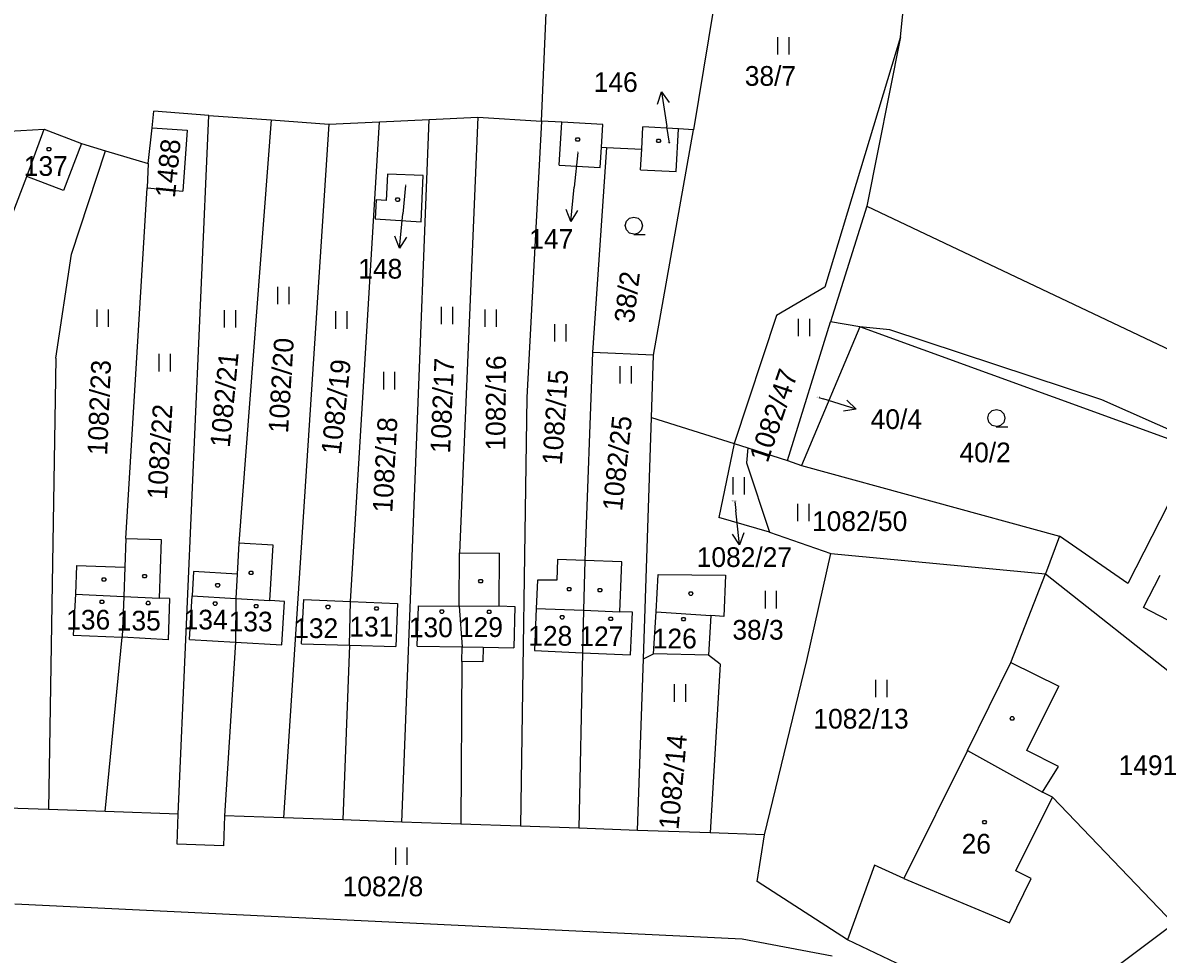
# Model space of a CAD drawing. Extents: x -850689 to -847910, y -1058374 to -1054747.
# Drawn here: x -849424.1 to -849326.1, y -1056255.5 to -1056175.1 of the extents above; entities that cross this region are included whole.
import ezdxf

# ---------------------------------------------------------------- set-up
doc = ezdxf.new("R2010")
doc.units = 0
for name, color, linetype in [('KN_HRANICE', 7, 'Continuous'), ('KN_KULTURY', 7, 'Continuous'), ('KN_PARCELY', 7, 'Continuous'), ('KN_SLUCKY', 7, 'Continuous'), ('KN_STAVEBNI', 7, 'Continuous')]:
    doc.layers.add(name, color=color, linetype=linetype)

# ---------------------------------------------------------------- blocks, each defined once
blk = doc.blocks.new('304')
blk.add_lwpolyline([(0, 0), (-0.38, 0.1), (-0.65, 0.37), (-0.75, 0.74), (-0.65, 1.11), (-0.38, 1.38), (-0.01, 1.48), (0.36, 1.38), (0.63, 1.11), (0.73, 0.73), (0.63, 0.35), (0.36, 0.08), (-0.02, -0.02), (0.98, -0.02)])
blk = doc.blocks.new('306')
for p, q in [((-0.5, 1.5), (-0.5, 0)), ((0.5, 0), (0.5, 1.5))]:
    blk.add_line(p, q)
blk = doc.blocks.new('NAHRADNI_SYMBOL')
blk.add_lwpolyline([(0.09, 0.15), (0.18, 0), (0.09, -0.15), (-0.09, -0.15), (-0.18, 0), (-0.09, 0.15), (0.09, 0.15)])
blk = doc.blocks.new('10292')
blk.add_line((0, 3), (0, 0))
blk.add_lwpolyline([(-0.5, 2), (0, 3), (0.5, 2)])
blk = doc.blocks.new('402')
blk.add_lwpolyline([(0.09, 0.15), (0.18, 0), (0.09, -0.15), (-0.09, -0.15), (-0.18, 0), (-0.09, 0.15), (0.09, 0.15)])

msp = doc.modelspace()

# ---------------------------------------------------------------- linework, layer by layer
at = {"layer": 'KN_HRANICE'}
for p, q in [((-849348.36, -1056176.35), (-849346.5, -1056157.31)), ((-849379.32, -1056183.62), (-849378.74, -1056169.41)), ((-849364.51, -1056173.91), (-849366.23, -1056184.36)), ((-849348.36, -1056176.35), (-849354.89, -1056197.95)), ((-849348.36, -1056176.35), (-849351.28, -1056190.95)), ((-849412.91, -1056184.19), (-849412.76, -1056182.77)), ((-849408.02, -1056183.12), (-849412.76, -1056182.77)), ((-849410.67, -1056243.39), (-849408.02, -1056183.12)), ((-849408.02, -1056183.12), (-849402.65, -1056183.52)), ((-849402.65, -1056183.52), (-849405.42, -1056220.02)), ((-849402.65, -1056183.52), (-849397.67, -1056183.89)), ((-849397.67, -1056183.89), (-849393.31, -1056183.68)), ((-849395.79, -1056225.05), (-849393.31, -1056183.68)), ((-849393.31, -1056183.68), (-849389.01, -1056183.48)), ((-849391.38, -1056244.07), (-849389.01, -1056183.48)), ((-849389.01, -1056183.48), (-849384.81, -1056183.28)), ((-849384.81, -1056183.28), (-849386.41, -1056220.84)), ((-849384.81, -1056183.28), (-849379.32, -1056183.62)), ((-849379.32, -1056183.62), (-849380.59, -1056207.46)), ((-849377.59, -1056183.72), (-849379.32, -1056183.62)), ((-849377.8, -1056187.41), (-849377.59, -1056183.72)), ((-849374.05, -1056183.92), (-849377.59, -1056183.72)), ((-849437.73, -1056185.24), (-849422.22, -1056184.31)), ((-849423.72, -1056188.39), (-849422.22, -1056184.31)), ((-849422.22, -1056184.31), (-849418.99, -1056185.55)), ((-849413.25, -1056187.28), (-849412.91, -1056184.19)), ((-849412.91, -1056184.19), (-849409.88, -1056184.39)), ((-849409.88, -1056184.39), (-849410.26, -1056189.65)), ((-849397.67, -1056183.89), (-849401.57, -1056243.71)), ((-849374.16, -1056185.87), (-849374.05, -1056183.92)), ((-849370.69, -1056186.03), (-849370.58, -1056184.12)), ((-849367.51, -1056184.29), (-849370.58, -1056184.12)), ((-849369.66, -1056203.79), (-849366.23, -1056184.36)), ((-849367.72, -1056187.96), (-849367.51, -1056184.29)), ((-849366.23, -1056184.36), (-849367.51, -1056184.29)), ((-849418.99, -1056185.55), (-849420.56, -1056189.61)), ((-849418.99, -1056185.55), (-849416.94, -1056186.17)), ((-849419.86, -1056195.08), (-849416.94, -1056186.17)), ((-849416.94, -1056186.17), (-849413.25, -1056187.28)), ((-849373.73, -1056185.89), (-849374.92, -1056203.58)), ((-849374.26, -1056187.61), (-849374.16, -1056185.87)), ((-849374.16, -1056185.87), (-849373.73, -1056185.89)), ((-849373.73, -1056185.89), (-849370.69, -1056186.03)), ((-849370.79, -1056187.81), (-849370.69, -1056186.03)), ((-849413.25, -1056187.28), (-849413.34, -1056189.38)), ((-849377.8, -1056187.41), (-849374.26, -1056187.61)), ((-849425.74, -1056193.65), (-849423.72, -1056188.39)), ((-849420.56, -1056189.61), (-849423.72, -1056188.39)), ((-849392.61, -1056188.18), (-849392.73, -1056190.46)), ((-849389.53, -1056188.31), (-849392.61, -1056188.18)), ((-849389.71, -1056192.31), (-849389.53, -1056188.31)), ((-849370.79, -1056187.81), (-849367.72, -1056187.96)), ((-849415.18, -1056219.61), (-849413.34, -1056189.38)), ((-849413.34, -1056189.38), (-849410.26, -1056189.65)), ((-849393.59, -1056190.4), (-849393.69, -1056192.04)), ((-849392.73, -1056190.46), (-849393.59, -1056190.4)), ((-849351.28, -1056190.95), (-849354.41, -1056200.92)), ((-849351.28, -1056190.95), (-849317.91, -1056206.78)), ((-849393.69, -1056192.04), (-849389.71, -1056192.31)), ((-849421.21, -1056204.05), (-849419.86, -1056195.08)), ((-849354.89, -1056197.95), (-849359.05, -1056200.39)), ((-849359.05, -1056200.39), (-849362.71, -1056211.43)), ((-849358.1, -1056212.88), (-849354.41, -1056200.92)), ((-849351.88, -1056201.36), (-849354.41, -1056200.92)), ((-849351.88, -1056201.36), (-849356.9, -1056213.31)), ((-849321.95, -1056212.23), (-849351.88, -1056201.36)), ((-849349.3, -1056201.62), (-849351.88, -1056201.36)), ((-849331, -1056207.66), (-849349.3, -1056201.62)), ((-849421.21, -1056204.05), (-849421.86, -1056243)), ((-849374.92, -1056203.58), (-849375.6, -1056221.52)), ((-849369.66, -1056203.79), (-849374.92, -1056203.58)), ((-849369.84, -1056209.17), (-849369.66, -1056203.79)), ((-849380.59, -1056207.46), (-849381.14, -1056244.42)), ((-849309.67, -1056217.15), (-849331, -1056207.66)), ((-849370.54, -1056230), (-849369.84, -1056209.17)), ((-849369.84, -1056209.17), (-849362.71, -1056211.43)), ((-849362.71, -1056211.43), (-849364.05, -1056217.8)), ((-849362.71, -1056211.43), (-849361.54, -1056211.8)), ((-849361.54, -1056211.8), (-849361.64, -1056213.08)), ((-849361.54, -1056211.8), (-849358.1, -1056212.88)), ((-849361.64, -1056213.08), (-849359.68, -1056219.08)), ((-849358.1, -1056212.88), (-849356.9, -1056213.31)), ((-849356.9, -1056213.31), (-849334.65, -1056219.42)), ((-849323.51, -1056213.18), (-849328.75, -1056223.5)), ((-849359.68, -1056219.08), (-849364.05, -1056217.8)), ((-849415.18, -1056219.61), (-849415.26, -1056222.08)), ((-849415.18, -1056219.61), (-849412.13, -1056219.71)), ((-849412.13, -1056219.71), (-849412.3, -1056224.75)), ((-849359.68, -1056219.08), (-849354.38, -1056220.91)), ((-849334.65, -1056219.42), (-849335.86, -1056222.66)), ((-849328.75, -1056223.5), (-849334.65, -1056219.42)), ((-849405.42, -1056220.02), (-849405.57, -1056222.7)), ((-849402.48, -1056220.19), (-849405.42, -1056220.02)), ((-849402.75, -1056224.96), (-849402.48, -1056220.19)), ((-849386.44, -1056225.44), (-849386.41, -1056220.84)), ((-849386.41, -1056220.84), (-849382.96, -1056220.88)), ((-849382.99, -1056225.42), (-849382.96, -1056220.88)), ((-849356.44, -1056230.13), (-849354.38, -1056220.91)), ((-849354.38, -1056220.91), (-849335.86, -1056222.66)), ((-849377.94, -1056221.42), (-849378.01, -1056223.21)), ((-849375.6, -1056221.52), (-849377.94, -1056221.42)), ((-849375.6, -1056221.52), (-849375.7, -1056225.8)), ((-849372.39, -1056221.63), (-849375.6, -1056221.52)), ((-849372.57, -1056225.93), (-849372.39, -1056221.63)), ((-849419.43, -1056221.94), (-849419.51, -1056224.41)), ((-849419.43, -1056221.94), (-849415.26, -1056222.08)), ((-849415.26, -1056222.08), (-849415.35, -1056224.61)), ((-849409.34, -1056222.47), (-849409.46, -1056224.57)), ((-849405.57, -1056222.7), (-849409.34, -1056222.47)), ((-849405.57, -1056222.7), (-849405.69, -1056224.8)), ((-849369.45, -1056225.94), (-849369.26, -1056222.73)), ((-849369.26, -1056222.73), (-849363.46, -1056222.79)), ((-849363.46, -1056222.79), (-849363.6, -1056226.34)), ((-849338.84, -1056230.31), (-849335.86, -1056222.66)), ((-849335.86, -1056222.66), (-849312.67, -1056241.03)), ((-849379.68, -1056223.2), (-849379.78, -1056225.64)), ((-849378.01, -1056223.21), (-849379.68, -1056223.2)), ((-849419.51, -1056224.41), (-849419.72, -1056227.94)), ((-849415.35, -1056224.61), (-849415.49, -1056228.13)), ((-849411.41, -1056224.78), (-849412.3, -1056224.75)), ((-849411.41, -1056224.78), (-849411.53, -1056228.36)), ((-849409.68, -1056228.34), (-849409.46, -1056224.57)), ((-849405.69, -1056224.8), (-849405.72, -1056228.57)), ((-849401.5, -1056225.04), (-849402.75, -1056224.96)), ((-849401.72, -1056228.8), (-849401.5, -1056225.04)), ((-849400.03, -1056228.7), (-849399.84, -1056224.88)), ((-849399.84, -1056224.88), (-849395.79, -1056225.05)), ((-849395.88, -1056228.82), (-849395.79, -1056225.05)), ((-849395.79, -1056225.05), (-849391.74, -1056225.22)), ((-849391.74, -1056225.22), (-849391.9, -1056228.93)), ((-849390.04, -1056228.91), (-849389.94, -1056225.41)), ((-849389.94, -1056225.41), (-849386.44, -1056225.44)), ((-849386.44, -1056225.44), (-849386.18, -1056228.97)), ((-849382.99, -1056225.42), (-849381.64, -1056225.49)), ((-849381.64, -1056225.49), (-849381.71, -1056229.04)), ((-849379.78, -1056225.64), (-849379.94, -1056229.28)), ((-849375.7, -1056225.8), (-849375.79, -1056229.47)), ((-849371.48, -1056225.97), (-849372.57, -1056225.93)), ((-849371.66, -1056229.64), (-849371.48, -1056225.97)), ((-849369.67, -1056229.55), (-849369.45, -1056225.94)), ((-849364.72, -1056226.27), (-849364.93, -1056229.68)), ((-849363.6, -1056226.34), (-849364.72, -1056226.27)), ((-849419.72, -1056227.94), (-849415.49, -1056228.13)), ((-849416.97, -1056243.16), (-849415.49, -1056228.13)), ((-849411.53, -1056228.36), (-849415.49, -1056228.13)), ((-849409.68, -1056228.34), (-849405.72, -1056228.57)), ((-849405.72, -1056228.57), (-849406.67, -1056243.53)), ((-849405.72, -1056228.57), (-849401.72, -1056228.8)), ((-849400.03, -1056228.7), (-849395.88, -1056228.82)), ((-849395.88, -1056228.82), (-849396.47, -1056243.89)), ((-849395.88, -1056228.82), (-849391.9, -1056228.93)), ((-849390.04, -1056228.91), (-849386.18, -1056228.97)), ((-849386.21, -1056230.22), (-849386.18, -1056228.97)), ((-849384.37, -1056229), (-849384.39, -1056230.25)), ((-849384.37, -1056229), (-849381.71, -1056229.04)), ((-849379.94, -1056229.28), (-849375.79, -1056229.47)), ((-849375.79, -1056229.47), (-849376.11, -1056244.6)), ((-849375.79, -1056229.47), (-849371.66, -1056229.64)), ((-849370.54, -1056230), (-849369.67, -1056229.55)), ((-849364.93, -1056229.68), (-849369.67, -1056229.55)), ((-849363.91, -1056230.46), (-849364.93, -1056229.68)), ((-849386.21, -1056230.22), (-849386.29, -1056244.24)), ((-849384.39, -1056230.25), (-849386.21, -1056230.22)), ((-849371.04, -1056244.79), (-849370.54, -1056230)), ((-849363.91, -1056230.46), (-849364.79, -1056245)), ((-849360.1, -1056245.17), (-849356.44, -1056230.13)), ((-849342.6, -1056237.89), (-849338.84, -1056230.31)), ((-849338.84, -1056230.31), (-849334.72, -1056232.36)), ((-849337.47, -1056237.91), (-849334.72, -1056232.36)), ((-849342.6, -1056237.89), (-849348.09, -1056248.94)), ((-849334.74, -1056239.27), (-849337.47, -1056237.91)), ((-849336.12, -1056241.5), (-849334.74, -1056239.27)), ((-849335.27, -1056241.92), (-849336.12, -1056241.5)), ((-849335.27, -1056241.92), (-849324.78, -1056252.85)), ((-849421.86, -1056243), (-849431.74, -1056242.65)), ((-849416.97, -1056243.16), (-849421.86, -1056243)), ((-849410.67, -1056243.39), (-849416.97, -1056243.16)), ((-849410.76, -1056245.99), (-849410.67, -1056243.39)), ((-849406.67, -1056243.53), (-849406.76, -1056246.13)), ((-849401.57, -1056243.71), (-849406.67, -1056243.53)), ((-849396.47, -1056243.89), (-849401.57, -1056243.71)), ((-849391.38, -1056244.07), (-849396.47, -1056243.89)), ((-849386.29, -1056244.24), (-849391.38, -1056244.07)), ((-849381.14, -1056244.42), (-849386.29, -1056244.24)), ((-849376.11, -1056244.6), (-849381.14, -1056244.42)), ((-849371.04, -1056244.79), (-849376.11, -1056244.6)), ((-849364.79, -1056245), (-849371.04, -1056244.79)), ((-849360.1, -1056245.17), (-849364.79, -1056245)), ((-849360.74, -1056249.21), (-849360.1, -1056245.17)), ((-849406.76, -1056246.13), (-849410.76, -1056245.99)), ((-849350.61, -1056247.78), (-849352.94, -1056254.24)), ((-849348.09, -1056248.94), (-849350.61, -1056247.78)), ((-849352.94, -1056254.24), (-849360.74, -1056249.21)), ((-849424.74, -1056251.13), (-849362.03, -1056254.15)), ((-849324.78, -1056252.85), (-849332.91, -1056258.92)), ((-849362.03, -1056254.15), (-849354.27, -1056255.62)), ((-849344.89, -1056258.04), (-849352.94, -1056254.24))]:
    msp.add_line(p, q, dxfattribs=at)
at = {"layer": 'KN_PARCELY'}
for p, q in [((-849368.3, -1056185.51), (-849368.52, -1056184.07)), ((-849376.21, -1056186.31), (-849376.51, -1056189.3)), ((-849391.05, -1056189.16), (-849391.29, -1056191.6)), ((-849355.4, -1056207.45), (-849355.04, -1056207.56)), ((-849362.65, -1056216.42), (-849362.57, -1056217.19))]:
    msp.add_line(p, q, dxfattribs=at)
at = {"layer": 'KN_SLUCKY'}
for p, q in [((-849327.41, -1056225.56), (-849325.97, -1056222.79)), ((-849419.51, -1056224.41), (-849415.35, -1056224.61)), ((-849415.35, -1056224.61), (-849412.3, -1056224.75)), ((-849409.46, -1056224.57), (-849405.69, -1056224.8)), ((-849405.69, -1056224.8), (-849402.75, -1056224.96)), ((-849386.44, -1056225.44), (-849382.99, -1056225.42)), ((-849379.78, -1056225.64), (-849375.7, -1056225.8)), ((-849375.7, -1056225.8), (-849372.57, -1056225.93)), ((-849322.77, -1056227.98), (-849327.41, -1056225.56)), ((-849369.45, -1056225.94), (-849364.72, -1056226.27)), ((-849386.18, -1056228.97), (-849384.37, -1056229)), ((-849342.6, -1056237.89), (-849336.12, -1056241.5)), ((-849338.43, -1056248.28), (-849335.27, -1056241.92)), ((-849337.09, -1056248.95), (-849338.43, -1056248.28)), ((-849348.09, -1056248.94), (-849340.37, -1056252.17)), ((-849338.98, -1056252.75), (-849337.09, -1056248.95)), ((-849340.37, -1056252.17), (-849338.98, -1056252.75))]:
    msp.add_line(p, q, dxfattribs=at)
at = {"layer": 'KN_STAVEBNI'}
for p, q in [((-849377.8, -1056187.41), (-849377.59, -1056183.72)), ((-849374.05, -1056183.92), (-849377.59, -1056183.72)), ((-849374.16, -1056185.87), (-849374.05, -1056183.92)), ((-849370.69, -1056186.03), (-849370.58, -1056184.12)), ((-849367.51, -1056184.29), (-849370.58, -1056184.12)), ((-849367.72, -1056187.96), (-849367.51, -1056184.29)), ((-849374.26, -1056187.61), (-849374.16, -1056185.87)), ((-849370.79, -1056187.81), (-849370.69, -1056186.03)), ((-849377.8, -1056187.41), (-849374.26, -1056187.61)), ((-849392.61, -1056188.18), (-849392.73, -1056190.46)), ((-849389.53, -1056188.31), (-849392.61, -1056188.18)), ((-849389.71, -1056192.31), (-849389.53, -1056188.31)), ((-849370.79, -1056187.81), (-849367.72, -1056187.96)), ((-849393.59, -1056190.4), (-849393.69, -1056192.04)), ((-849392.73, -1056190.46), (-849393.59, -1056190.4)), ((-849393.69, -1056192.04), (-849389.71, -1056192.31)), ((-849419.51, -1056224.41), (-849419.72, -1056227.94)), ((-849419.51, -1056224.41), (-849415.35, -1056224.61)), ((-849415.35, -1056224.61), (-849415.49, -1056228.13)), ((-849415.35, -1056224.61), (-849415.49, -1056228.13)), ((-849415.35, -1056224.61), (-849412.3, -1056224.75)), ((-849411.41, -1056224.78), (-849412.3, -1056224.75)), ((-849411.41, -1056224.78), (-849411.53, -1056228.36)), ((-849409.68, -1056228.34), (-849409.46, -1056224.57)), ((-849409.46, -1056224.57), (-849405.69, -1056224.8)), ((-849405.69, -1056224.8), (-849405.72, -1056228.57)), ((-849405.69, -1056224.8), (-849405.72, -1056228.57)), ((-849405.69, -1056224.8), (-849402.75, -1056224.96)), ((-849401.5, -1056225.04), (-849402.75, -1056224.96)), ((-849401.72, -1056228.8), (-849401.5, -1056225.04)), ((-849400.03, -1056228.7), (-849399.84, -1056224.88)), ((-849399.84, -1056224.88), (-849395.79, -1056225.05)), ((-849395.88, -1056228.82), (-849395.79, -1056225.05)), ((-849395.88, -1056228.82), (-849395.79, -1056225.05)), ((-849395.79, -1056225.05), (-849391.74, -1056225.22)), ((-849391.74, -1056225.22), (-849391.9, -1056228.93)), ((-849390.04, -1056228.91), (-849389.94, -1056225.41)), ((-849389.94, -1056225.41), (-849386.44, -1056225.44)), ((-849386.44, -1056225.44), (-849382.99, -1056225.42)), ((-849386.44, -1056225.44), (-849386.18, -1056228.97)), ((-849386.44, -1056225.44), (-849386.18, -1056228.97)), ((-849382.99, -1056225.42), (-849381.64, -1056225.49)), ((-849381.64, -1056225.49), (-849381.71, -1056229.04)), ((-849379.78, -1056225.64), (-849379.94, -1056229.28)), ((-849379.78, -1056225.64), (-849375.7, -1056225.8)), ((-849375.7, -1056225.8), (-849375.79, -1056229.47)), ((-849375.7, -1056225.8), (-849375.79, -1056229.47)), ((-849375.7, -1056225.8), (-849372.57, -1056225.93)), ((-849371.48, -1056225.97), (-849372.57, -1056225.93)), ((-849371.66, -1056229.64), (-849371.48, -1056225.97)), ((-849369.67, -1056229.55), (-849369.45, -1056225.94)), ((-849369.45, -1056225.94), (-849364.72, -1056226.27)), ((-849364.72, -1056226.27), (-849364.93, -1056229.68)), ((-849419.72, -1056227.94), (-849415.49, -1056228.13)), ((-849411.53, -1056228.36), (-849415.49, -1056228.13)), ((-849409.68, -1056228.34), (-849405.72, -1056228.57)), ((-849405.72, -1056228.57), (-849401.72, -1056228.8)), ((-849400.03, -1056228.7), (-849395.88, -1056228.82)), ((-849395.88, -1056228.82), (-849391.9, -1056228.93)), ((-849390.04, -1056228.91), (-849386.18, -1056228.97)), ((-849386.18, -1056228.97), (-849384.37, -1056229)), ((-849384.37, -1056229), (-849381.71, -1056229.04)), ((-849379.94, -1056229.28), (-849375.79, -1056229.47)), ((-849375.79, -1056229.47), (-849371.66, -1056229.64)), ((-849364.93, -1056229.68), (-849369.67, -1056229.55)), ((-849342.6, -1056237.89), (-849348.09, -1056248.94)), ((-849342.6, -1056237.89), (-849336.12, -1056241.5)), ((-849335.27, -1056241.92), (-849336.12, -1056241.5)), ((-849338.43, -1056248.28), (-849335.27, -1056241.92)), ((-849337.09, -1056248.95), (-849338.43, -1056248.28)), ((-849348.09, -1056248.94), (-849340.37, -1056252.17)), ((-849338.98, -1056252.75), (-849337.09, -1056248.95)), ((-849340.37, -1056252.17), (-849338.98, -1056252.75))]:
    msp.add_line(p, q, dxfattribs=at)

# ---------------------------------------------------------------- block references
at = {"layer": 'KN_KULTURY'}
for name, p in [('306', (-849358.48, -1056177.87)), ('402', (-849376.21, -1056185.21)), ('402', (-849369.23, -1056185.32)), ('NAHRADNI_SYMBOL', (-849421.81, -1056186.03)), ('402', (-849391.74, -1056190.39)), ('304', (-849371.36, -1056193.37)), ('306', (-849401.59, -1056199.4)), ('306', (-849417.18, -1056201.37)), ('306', (-849406.2, -1056201.41)), ('306', (-849396.6, -1056201.52)), ('306', (-849387.49, -1056201.13)), ('306', (-849383.72, -1056201.36)), ('306', (-849377.7, -1056202.62)), ('306', (-849356.68, -1056202.17)), ('306', (-849411.82, -1056205.2)), ('306', (-849392.47, -1056206.75)), ('306', (-849372.08, -1056206.24)), ('304', (-849340.09, -1056209.96)), ('306', (-849362.32, -1056215.83)), ('306', (-849356.75, -1056218.12)), ('402', (-849413.56, -1056222.87)), ('402', (-849404.38, -1056222.57)), ('402', (-849417.07, -1056223.15)), ('402', (-849407.26, -1056223.65)), ('402', (-849384.58, -1056223.29)), ('402', (-849376.94, -1056223.98)), ('402', (-849374.29, -1056224.07)), ('402', (-849366.45, -1056224.37)), ('306', (-849359.55, -1056225.64)), ('402', (-849417.24, -1056225.07)), ('402', (-849413.25, -1056225.18)), ('402', (-849407.47, -1056225.23)), ('402', (-849403.94, -1056225.45)), ('402', (-849397.74, -1056225.52)), ('402', (-849393.56, -1056225.66)), ('402', (-849387.93, -1056225.92)), ('402', (-849383.85, -1056225.94)), ('402', (-849377.55, -1056226.41)), ('402', (-849373.36, -1056226.54)), ('402', (-849367.09, -1056226.58)), ('306', (-849367.39, -1056233.69)), ('306', (-849350.01, -1056233.31)), ('402', (-849338.74, -1056235.13)), ('402', (-849341.13, -1056244.08)), ('306', (-849391.43, -1056247.77))]:
    msp.add_blockref(name, p, dxfattribs=at)
at = {"layer": 'KN_PARCELY'}
for p, rotation in [((-849368.52, -1056184.07), 8.651663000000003), ((-849376.51, -1056189.3), 174.29376100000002), ((-849391.29, -1056191.6), 174.408353), ((-849355.04, -1056207.56), -107.55479500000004), ((-849362.57, -1056217.19), -174.075195)]:
    msp.add_blockref('10292', p, dxfattribs=dict(at, rotation=rotation))

# ---------------------------------------------------------------- texts
for s, height, p in [('38/7', 1.7, (-849361.799, -1056180.57)), ('146', 1.7, (-849374.824, -1056181.1)), ('146', 0.1, (-849368.45, -1056185.51)), ('137', 1.7, (-849423.98, -1056188.34)), ('147', 0.1, (-849376.36, -1056186.31)), ('148', 0.1, (-849391.2, -1056189.16)), ('147', 1.7, (-849380.384, -1056194.63)), ('148', 1.7, (-849395.134, -1056197.2)), ('40/4', 0.1, (-849355.598, -1056207.45)), ('40/4', 1.7, (-849350.94, -1056210.17)), ('40/2', 1.7, (-849343.279, -1056213.04)), ('1082/27', 0.1, (-849362.995, -1056216.42)), ('1082/50', 1.7, (-849355.999, -1056218.97)), ('1082/27', 1.7, (-849365.94, -1056222.07)), ('136', 1.7, (-849420.32, -1056227.47)), ('135', 1.7, (-849415.96, -1056227.55)), ('134', 1.7, (-849410.19, -1056227.46)), ('133', 1.7, (-849406.31, -1056227.63)), ('132', 1.7, (-849400.66, -1056228.2)), ('131', 1.7, (-849395.897, -1056228.07)), ('130', 1.7, (-849390.77, -1056228.13)), ('129', 1.7, (-849386.45, -1056228.11)), ('38/3', 1.7, (-849362.869, -1056228.34)), ('128', 1.7, (-849380.47, -1056228.86)), ('127', 1.7, (-849376.06, -1056228.9)), ('126', 1.7, (-849369.73, -1056229.09)), ('1082/13', 1.7, (-849355.879, -1056236.01)), ('1491', 1.7, (-849329.557, -1056240.02)), ('26', 1.7, (-849343.099, -1056246.79)), ('1082/8', 1.7, (-849396.48, -1056250.47))]:
    msp.add_text(s, height=height, dxfattribs=at).set_placement(p)
for s, rotation, p in [('1488', 84.168, (-849410.951, -1056190.282)), ('38/2', 82.964, (-849371.377, -1056201.094)), ('1082/20', 86.459, (-849401.192, -1056210.568)), ('1082/21', 84.569, (-849406.223, -1056211.811)), ('1082/19', 83.766, (-849396.653, -1056212.434)), ('1082/17', 87.491, (-849387.217, -1056212.293)), ('1082/16', 89.611, (-849382.45, -1056212.039)), ('1082/23', 87.605, (-849416.795, -1056212.464)), ('1082/15', 86.116, (-849377.578, -1056213.316)), ('1082/47', 71.276, (-849359.834, -1056213.158)), ('1082/22', 86.517, (-849411.647, -1056216.288)), ('1082/25', 83.996, (-849372.384, -1056217.297)), ('1082/18', 86.86, (-849392.201, -1056217.41)), ('1082/14', 84.74, (-849367.522, -1056244.775))]:
    msp.add_text(s, height=1.7, rotation=rotation, dxfattribs=at).set_placement(p)

doc.saveas('drawing.dxf')
